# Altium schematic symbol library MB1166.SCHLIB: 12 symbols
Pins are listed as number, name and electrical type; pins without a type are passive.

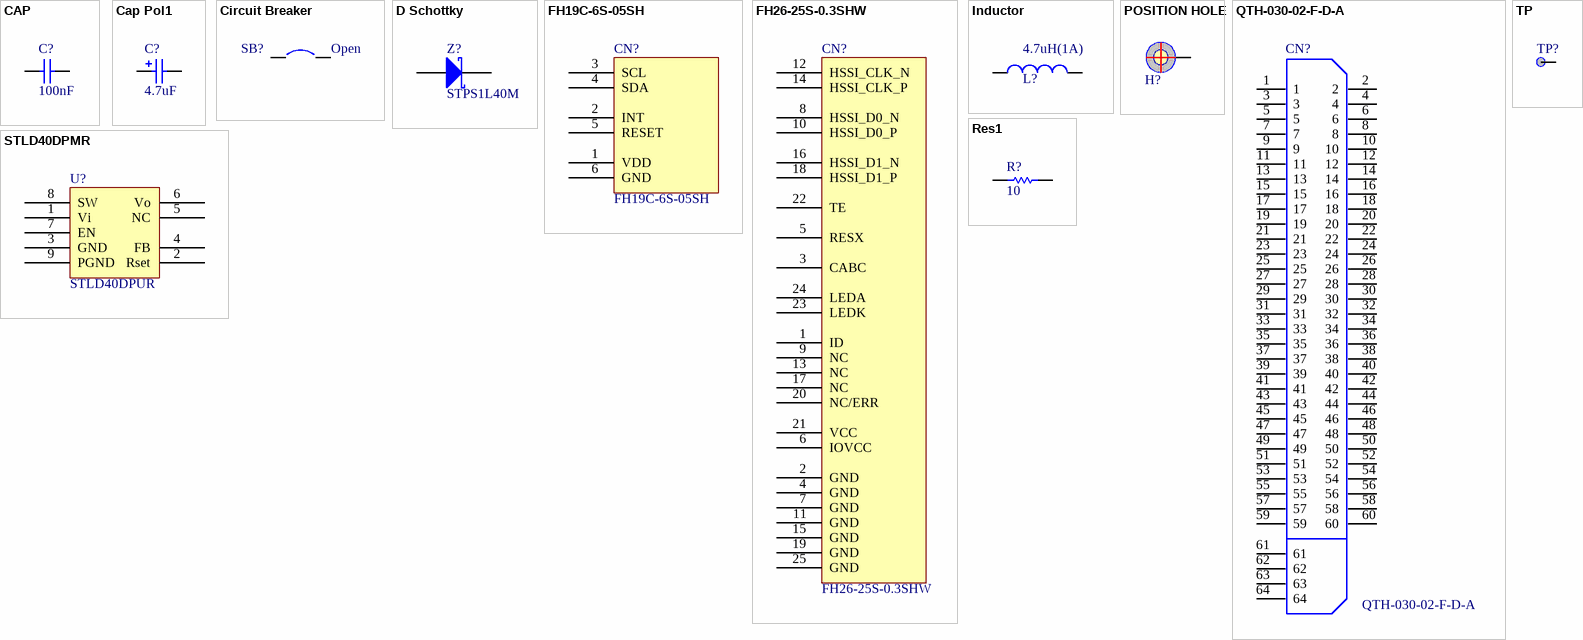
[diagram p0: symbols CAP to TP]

## CAP
designator C?, comment 100nF
Capacitor; Value: 100pF
footprint RAD-0.3 (Capacitor; 2 Leads)
simulation model CAP (Capacitor)
signal-integrity model Cap
footprint CAPR5.08-7.8X3.2
footprint CAPR2.54-5.1X3.2
footprint 0603
footprint 0603 (Footprint not found)
footprint 0603C
footprint 0402C
pins: 1, 2

## Cap Pol1
designator C?, comment 4.7uF
Polarized Capacitor (Radial); Value: 100pF
footprint TAN-B (Footprint not found)
simulation model CAP (Capacitor)
signal-integrity model Cap Pol
footprint CAPPR1.5-4X5
footprint CAPPR1.27-1.96X4.06
footprint CAPPR2-5X6.8
footprint CAPPR5-5X5
footprint CAPPR7.5-16X35
footprint TAN-A
footprint 1206C
pins: 1, 2

## Circuit Breaker
designator SB?, comment Open
Circuit Breaker
footprint SPST-2 (Circuit Breaker; 2 Leads)
footprint JP2_SMD
footprint SB_0603 (Footprint not found)
pins: 1, 2

## D Schottky
designator Z?, comment STPS1L40M
Schottky Diode; Code - JEDEC: DO-214-AA
footprint 1R1C (Footprint not found)
footprint DO216AA
footprint DO-216AA (Footprint not found)
pins: 1 A, 2 K

## FH19C-6S-05SH
designator CN?
footprint FH19C-6S-05SH (Footprint not found)
pins: 1 VDD, 2 INT, 3 SCL, 4 SDA, 5 RESET, 6 GND

## FH26-25S-0.3SHW
designator CN?
footprint FH26-25S-0.3SHW (Footprint not found)
pins: 1 ID, 2 GND, 3 CABC, 4 GND, 5 RESX, 6 IOVCC, 7 GND, 8 HSSI_D0_N, 9 NC, 10 HSSI_D0_P, 11 GND, 12 HSSI_CLK_N, 13 NC, 14 HSSI_CLK_P, 15 GND, 16 HSSI_D1_N, 17 NC, 18 HSSI_D1_P, 19 GND, 20 NC/ERR, 21 VCC, 22 TE, 23 LEDK, 24 LEDA, 25 GND

## Inductor
designator L?, comment 4.7uH(1A)
Inductor; Value: 100uH
footprint 3225 (Footprint not found)
footprint 3225L
footprint LSM2_3R2X2R5_H1R55 (Footprint not found)
footprint 1210L (Footprint not found)
pins: 1, 2

## POSITION HOLE
designator H?  (value not drawn)
footprint HOLE_C9D4R5 (Footprint not found)
pins: 1

## QTH-030-02-F-D-A
designator CN?
HIGH SPEED TERMINAL STRIP, .5mm PITCH, 60 PINS.; MANUFACTURER: SAMTEC; PCB DECAL: QTH-030-02-X-D-A
footprint QTH-030-02-F-D-A (Footprint not found)
pins: 1, 2, 3, 4, 5, 6, 7, 8, 9, 10, 11, 12, 13, 14, 15, 16, 17, 18, 19, 20, 21, 22, 23, 24, 25, 26, 27, 28, 29, 30, 31, 32, 33, 34, 35, 36, 37, 38, 39, 40, 41, 42, 43, 44, 45, 46, 47, 48, 49, 50, 51, 52, 53, 54, 55, 56, 57, 58, 59, 60, 61, 62, 63, 64

## Res1
designator R?, comment 10
Resistor; Value: 1K
footprint AXIAL-0.3 (Resistor; 2 Leads)
simulation model RESISTOR (Resistor)
signal-integrity model Res
footprint 0603
footprint 0603R
pins: 1, 2
1 alternate drawing of the same symbol

## STLD40DPMR
designator U?, comment STLD40DPUR
footprint QFN8 (Footprint not found)
footprint QFNT8
footprint SON8_0R65_3X3 (Footprint not found)
footprint SON8_0R65_3X3_ST (Footprint not found)
pins: 1 Vi, 2 Rset, 3 GND, 4 FB, 5 NC, 6 Vo, 7 EN, 8 SW, 9 PGND

## TP
designator TP?
footprint TP
pins: 1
